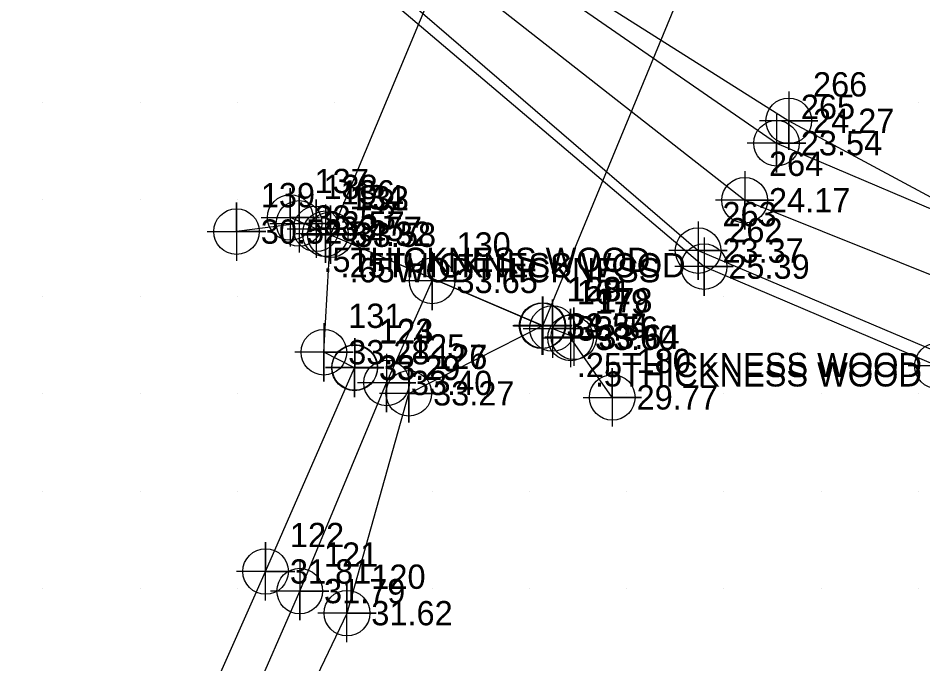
# Model space of a CAD drawing. Extents: x 2204340 to 2204783, y 268170 to 268760.
# Drawn here: x 2204477.4 to 2204570.5, y 268402.2 to 268468.7 of the extents above; entities that cross this region are included whole.
import ezdxf

# ---------------------------------------------------------------- set-up
doc = ezdxf.new("R2010")
doc.units = 0
for name, color, linetype in [('Exist DTM Breakline', 7, 'Continuous'), ('Exist DTM Breakline Cogo Elevation', 7, 'Continuous'), ('Exist DTM Breakline Cogo Number', 7, 'Continuous'), ('Exist DTM Breakline Cogo Point CELL', 7, 'Continuous'), ('Exist DTM Breakline Underwater', 7, 'Continuous'), ('Exist DTM Breakline Underwater Cogo Elevation', 7, 'Continuous'), ('Exist DTM Breakline Underwater Cogo Number', 7, 'Continuous'), ('Exist DTM Breakline Underwater Cogo Point CELL', 7, 'Continuous'), ('Exist DTM Crownline', 7, 'Continuous'), ('Exist DTM Crownline Cogo Elevation', 7, 'Continuous'), ('Exist DTM Crownline Cogo Number', 7, 'Continuous'), ('Exist DTM Crownline Cogo Point CELL', 7, 'Continuous'), ('Exist DTM QL2 LIDAR Elevation Point', 7, 'Continuous'), ('Exist Hydro Jurisdictional Stream or Body of Water', 7, 'Continuous'), ('Exist Roads Change in Surface', 7, 'Continuous'), ('Exist Roads Change in Surface Cogo Comment', 7, 'Continuous'), ('Exist Roads Change in Surface Cogo Elevation', 7, 'Continuous'), ('Exist Roads Change in Surface Cogo Number', 7, 'Continuous'), ('Exist Roads Change in Surface Cogo Point CELL', 7, 'Continuous'), ('Exist Roads EOP', 7, 'Continuous'), ('Exist Roads EOP Cogo Elevation', 7, 'Continuous'), ('Exist Roads EOP Cogo Number', 7, 'Continuous'), ('Exist Roads EOP Cogo Point CELL', 7, 'Continuous'), ('Exist Roads Soil', 7, 'Continuous'), ('Exist Roads Soil Cogo Elevation', 7, 'Continuous'), ('Exist Roads Soil Cogo Number', 7, 'Continuous'), ('Exist Roads Soil Cogo Point CELL', 7, 'Continuous'), ('Exist Structure Major Bridge WW', 7, 'Continuous'), ('Exist Structure Major Bridge WW Cogo Comment', 7, 'Continuous'), ('Exist Structure Major Bridge WW Cogo Elevation', 7, 'Continuous'), ('Exist Structure Major Bridge WW Cogo Number', 7, 'Continuous'), ('Exist Structure Major Bridge WW Cogo Point CELL', 7, 'Continuous'), ('Exist Structure Major Deck Tunnel Box Culvert', 7, 'Continuous'), ('Exist Structure Major Deck Tunnel Box Culvert Cogo Elevation', 7, 'Continuous'), ('Exist Structure Major Deck Tunnel Box Culvert Cogo Number', 7, 'Continuous'), ('Exist Structure Major Deck Tunnel Box Culvert Cogo Point CELL', 7, 'Continuous')]:
    doc.layers.add(name, color=color, linetype=linetype)

msp = doc.modelspace()

# ---------------------------------------------------------------- linework, layer by layer
at = {"layer": 'Exist DTM Breakline'}
for points in [[(2204442.107, 268518.107), (2204480.821, 268501.799), (2204502.532, 268495.779), (2204515.271, 268483.58), (2204555.414, 268455.782), (2204577.652, 268446.314), (2204630.936, 268427.717)], [(2204435.36, 268505.622), (2204480.446, 268489.144), (2204494.514, 268488.53), (2204511.374, 268475.793), (2204547.352, 268444.739), (2204573.727, 268433.567), (2204620.125, 268409.581)]]:
    msp.add_lwpolyline(points, dxfattribs=at)
at = {"layer": 'Exist DTM Breakline Cogo Point CELL'}
for points in [[(2204556.668, 268461.091), (2204556.668, 268455.091), (2204556.668, 268458.091), (2204559.668, 268458.091), (2204553.668, 268458.091)], [(2204555.413, 268458.782), (2204555.413, 268452.782), (2204555.413, 268455.782), (2204558.413, 268455.782), (2204552.413, 268455.782)], [(2204547.351, 268447.739), (2204547.351, 268441.739), (2204547.351, 268444.739), (2204550.351, 268444.739), (2204544.351, 268444.739)], [(2204547.96, 268446.09), (2204547.96, 268440.09), (2204547.96, 268443.09), (2204550.96, 268443.09), (2204544.96, 268443.09)], [(2204571.955, 268435.882), (2204571.955, 268429.882), (2204571.955, 268432.882), (2204574.955, 268432.882), (2204568.955, 268432.882)]]:
    msp.add_lwpolyline(points, dxfattribs=at)
for centre in [(2204556.668, 268458.091), (2204555.413, 268455.782), (2204547.351, 268444.739), (2204547.96, 268443.09), (2204571.955, 268432.882)]:
    msp.add_circle(centre, 2.344, dxfattribs=at)
at = {"layer": 'Exist DTM Breakline Underwater'}
msp.add_lwpolyline([(2204438.584, 268512.919), (2204481.572, 268495.841), (2204497.204, 268490.895), (2204514.255, 268479.669), (2204552.142, 268449.916), (2204575.996, 268440.349), (2204624.811, 268416.779)], dxfattribs=at)
at = {"layer": 'Exist DTM Breakline Underwater Cogo Point CELL'}
msp.add_lwpolyline([(2204552.141, 268452.916), (2204552.141, 268446.916), (2204552.141, 268449.916), (2204555.141, 268449.916), (2204549.141, 268449.916)], dxfattribs=at)
msp.add_circle((2204552.141, 268449.916), 2.344, dxfattribs=at)
at = {"layer": 'Exist DTM Crownline'}
msp.add_lwpolyline([(2204485.434, 268361.69), (2204506.392, 268409.717), (2204515.328, 268431.127), (2204520.013, 268441.62)], dxfattribs=at)
at = {"layer": 'Exist DTM Crownline Cogo Point CELL'}
for points in [[(2204520.012, 268444.62), (2204520.012, 268438.62), (2204520.012, 268441.62), (2204523.012, 268441.62), (2204517.012, 268441.62)], [(2204515.327, 268434.128), (2204515.327, 268428.128), (2204515.327, 268431.128), (2204518.327, 268431.128), (2204512.327, 268431.128)], [(2204506.391, 268412.716), (2204506.391, 268406.716), (2204506.391, 268409.716), (2204509.391, 268409.716), (2204503.391, 268409.716)]]:
    msp.add_lwpolyline(points, dxfattribs=at)
for centre in [(2204520.012, 268441.62), (2204515.327, 268431.128), (2204506.391, 268409.716)]:
    msp.add_circle(centre, 2.344, dxfattribs=at)
at = {"layer": 'Exist DTM QL2 LIDAR Elevation Point'}
for p, q in [((2204480, 268460), (2204480, 268460)), ((2204490, 268460), (2204490, 268460)), ((2204500, 268460), (2204500, 268460)), ((2204510, 268460), (2204510, 268460)), ((2204560, 268460), (2204560, 268460)), ((2204570, 268460), (2204570, 268460)), ((2204480, 268450), (2204480, 268450)), ((2204490, 268450), (2204490, 268450)), ((2204500, 268450), (2204500, 268450)), ((2204510, 268450), (2204510, 268450)), ((2204480, 268440), (2204480, 268440)), ((2204490, 268440), (2204490, 268440)), ((2204500, 268440), (2204500, 268440)), ((2204540, 268440), (2204540, 268440)), ((2204550, 268440), (2204550, 268440)), ((2204480, 268430), (2204480, 268430)), ((2204490, 268430), (2204490, 268430)), ((2204500, 268430), (2204500, 268430)), ((2204530, 268430), (2204530, 268430)), ((2204540, 268430), (2204540, 268430)), ((2204550, 268430), (2204550, 268430)), ((2204560, 268430), (2204560, 268430)), ((2204570, 268430), (2204570, 268430)), ((2204480, 268420), (2204480, 268420)), ((2204490, 268420), (2204490, 268420)), ((2204500, 268420), (2204500, 268420)), ((2204520, 268420), (2204520, 268420)), ((2204530, 268420), (2204530, 268420)), ((2204540, 268420), (2204540, 268420)), ((2204550, 268420), (2204550, 268420)), ((2204560, 268420), (2204560, 268420)), ((2204570, 268420), (2204570, 268420)), ((2204480, 268410), (2204480, 268410)), ((2204490, 268410), (2204490, 268410)), ((2204500, 268410), (2204500, 268410)), ((2204520, 268410), (2204520, 268410)), ((2204530, 268410), (2204530, 268410)), ((2204540, 268410), (2204540, 268410)), ((2204550, 268410), (2204550, 268410)), ((2204560, 268410), (2204560, 268410)), ((2204570, 268410), (2204570, 268410))]:
    msp.add_line(p, q, dxfattribs=at)
at = {"layer": 'Exist Hydro Jurisdictional Stream or Body of Water'}
for points in [[(2204442.883, 268520.114), (2204480.525, 268503.556), (2204503.227, 268495.899), (2204516.012, 268483.845), (2204556.669, 268458.091), (2204576.766, 268447.287), (2204631.194, 268429.043)], [(2204434.671, 268504.229), (2204475.094, 268482.789), (2204492.089, 268478.069), (2204511.02, 268474.48), (2204547.961, 268443.09), (2204571.955, 268432.882), (2204619.17, 268408.087)]]:
    msp.add_lwpolyline(points, dxfattribs=at)
at = {"layer": 'Exist Roads Change in Surface'}
msp.add_line((2204509.544, 268446.37), (2204531.394, 268437.027), dxfattribs=at)
at = {"layer": 'Exist Roads Change in Surface Cogo Point CELL'}
for points in [[(2204509.029, 268449.474), (2204509.029, 268443.474), (2204509.029, 268446.474), (2204512.029, 268446.474), (2204506.029, 268446.474)], [(2204531.311, 268440.011), (2204531.311, 268434.011), (2204531.311, 268437.011), (2204534.311, 268437.011), (2204528.311, 268437.011)]]:
    msp.add_lwpolyline(points, dxfattribs=at)
for centre in [(2204509.029, 268446.474), (2204531.311, 268437.011)]:
    msp.add_circle(centre, 2.344, dxfattribs=at)
at = {"layer": 'Exist Roads EOP'}
for points in [[(2204512.037, 268432.663), (2204508.88, 268434.285), (2204509.544, 268446.37)], [(2204517.609, 268430.056), (2204531.394, 268437.027)]]:
    msp.add_lwpolyline(points, dxfattribs=at)
at = {"layer": 'Exist Roads EOP Cogo Point CELL'}
for points in [[(2204509.543, 268449.369), (2204509.543, 268443.369), (2204509.543, 268446.369), (2204512.543, 268446.369), (2204506.543, 268446.369)], [(2204531.393, 268440.026), (2204531.393, 268434.026), (2204531.393, 268437.026), (2204534.393, 268437.026), (2204528.393, 268437.026)], [(2204508.88, 268437.285), (2204508.88, 268431.285), (2204508.88, 268434.285), (2204511.88, 268434.285), (2204505.88, 268434.285)], [(2204512.037, 268435.664), (2204512.037, 268429.664), (2204512.037, 268432.664), (2204515.037, 268432.664), (2204509.037, 268432.664)], [(2204517.608, 268433.056), (2204517.608, 268427.056), (2204517.608, 268430.056), (2204520.608, 268430.056), (2204514.608, 268430.056)]]:
    msp.add_lwpolyline(points, dxfattribs=at)
for centre in [(2204509.543, 268446.369), (2204531.393, 268437.026), (2204508.88, 268434.285), (2204512.037, 268432.664), (2204517.608, 268430.056)]:
    msp.add_circle(centre, 2.344, dxfattribs=at)
at = {"layer": 'Exist Roads Soil'}
for points in [[(2204481.307, 268363.121), (2204502.888, 268411.733), (2204512.03, 268432.667)], [(2204488.581, 268360.035), (2204511.257, 268407.444), (2204517.609, 268430.056)]]:
    msp.add_lwpolyline(points, dxfattribs=at)
at = {"layer": 'Exist Roads Soil Cogo Point CELL'}
for points in [[(2204512.055, 268429.724), (2204512.055, 268435.724), (2204512.055, 268432.724), (2204515.055, 268432.724), (2204509.055, 268432.724)], [(2204517.608, 268427.056), (2204517.608, 268433.056), (2204517.608, 268430.056), (2204520.608, 268430.056), (2204514.608, 268430.056)], [(2204502.888, 268408.733), (2204502.888, 268414.733), (2204502.888, 268411.733), (2204505.888, 268411.733), (2204499.888, 268411.733)], [(2204511.256, 268404.443), (2204511.256, 268410.443), (2204511.256, 268407.443), (2204514.256, 268407.443), (2204508.256, 268407.443)]]:
    msp.add_lwpolyline(points, dxfattribs=at)
for centre in [(2204512.055, 268432.724), (2204517.608, 268430.056), (2204502.888, 268411.733), (2204511.256, 268407.443)]:
    msp.add_circle(centre, 2.344, dxfattribs=at)
at = {"layer": 'Exist Structure Major Bridge WW'}
for points in [[(2204508.089, 268446.982), (2204505.422, 268448.148)], [(2204506.329, 268447.54), (2204499.897, 268446.696)], [(2204532.386, 268436.722), (2204534.586, 268435.88)], [(2204538.529, 268429.64), (2204534.242, 268435.758)]]:
    msp.add_lwpolyline(points, dxfattribs=at)
at = {"layer": 'Exist Structure Major Bridge WW Cogo Point CELL'}
for points in [[(2204502.422, 268448.148), (2204508.422, 268448.148), (2204505.422, 268448.148), (2204505.422, 268451.148), (2204505.422, 268445.148)], [(2204503.329, 268447.54), (2204509.329, 268447.54), (2204506.329, 268447.54), (2204506.329, 268450.54), (2204506.329, 268444.54)], [(2204496.896, 268446.696), (2204502.896, 268446.696), (2204499.896, 268446.696), (2204499.896, 268449.696), (2204499.896, 268443.696)], [(2204505.089, 268446.982), (2204511.089, 268446.982), (2204508.089, 268446.982), (2204508.089, 268449.982), (2204508.089, 268443.982)], [(2204529.385, 268436.722), (2204535.385, 268436.722), (2204532.385, 268436.722), (2204532.385, 268439.722), (2204532.385, 268433.722)], [(2204531.241, 268435.758), (2204537.241, 268435.758), (2204534.241, 268435.758), (2204534.241, 268438.758), (2204534.241, 268432.758)], [(2204531.586, 268435.88), (2204537.586, 268435.88), (2204534.586, 268435.88), (2204534.586, 268438.88), (2204534.586, 268432.88)], [(2204535.529, 268429.64), (2204541.529, 268429.64), (2204538.529, 268429.64), (2204538.529, 268432.64), (2204538.529, 268426.64)]]:
    msp.add_lwpolyline(points, dxfattribs=at)
for centre in [(2204505.422, 268448.148), (2204506.329, 268447.54), (2204499.896, 268446.696), (2204508.089, 268446.982), (2204532.385, 268436.722), (2204534.241, 268435.758), (2204534.586, 268435.88), (2204538.529, 268429.64)]:
    msp.add_circle(centre, 2.344, dxfattribs=at)
at = {"layer": 'Exist Structure Major Deck Tunnel Box Culvert'}
msp.add_lwpolyline([(2204531.382, 268437.017), (2204551.027, 268484.531), (2204529.29, 268493.682), (2204509.543, 268446.369)], close=True, dxfattribs=at)
at = {"layer": 'Exist Structure Major Deck Tunnel Box Culvert Cogo Point CELL'}
for points in [[(2204506.543, 268446.369), (2204512.543, 268446.369), (2204509.543, 268446.369), (2204509.543, 268449.369), (2204509.543, 268443.369)], [(2204528.382, 268437.017), (2204534.382, 268437.017), (2204531.382, 268437.017), (2204531.382, 268440.017), (2204531.382, 268434.017)]]:
    msp.add_lwpolyline(points, dxfattribs=at)
for centre in [(2204509.543, 268446.369), (2204531.382, 268437.017)]:
    msp.add_circle(centre, 2.344, dxfattribs=at)

# ---------------------------------------------------------------- texts
at = {"layer": 'Exist DTM Breakline Cogo Elevation'}
for s, p in [('24.27', (2204559.168, 268456.841)), ('23.54', (2204557.913, 268454.532)), ('23.37', (2204549.851, 268443.489)), ('25.39', (2204550.46, 268441.84))]:
    msp.add_text(s, height=2.5, dxfattribs=at).set_placement(p)
at = {"layer": 'Exist DTM Breakline Cogo Number'}
for s, p in [('266', (2204559.168, 268460.591)), ('265', (2204557.913, 268458.282)), ('263', (2204549.851, 268447.239)), ('262', (2204550.46, 268445.59))]:
    msp.add_text(s, height=2.5, dxfattribs=at).set_placement(p)
at = {"layer": 'Exist DTM Breakline Underwater Cogo Elevation'}
msp.add_text('24.17', height=2.5, dxfattribs=at).set_placement((2204554.641, 268448.666))
at = {"layer": 'Exist DTM Breakline Underwater Cogo Number'}
msp.add_text('264', height=2.5, dxfattribs=at).set_placement((2204554.641, 268452.416))
at = {"layer": 'Exist DTM Crownline Cogo Elevation'}
for s, p in [('33.65', (2204522.512, 268440.37)), ('33.40', (2204517.827, 268429.878)), ('31.79', (2204508.891, 268408.466))]:
    msp.add_text(s, height=2.5, dxfattribs=at).set_placement(p)
at = {"layer": 'Exist DTM Crownline Cogo Number'}
for s, p in [('130', (2204522.512, 268444.12)), ('125', (2204517.827, 268433.628)), ('121', (2204508.891, 268412.216))]:
    msp.add_text(s, height=2.5, dxfattribs=at).set_placement(p)
at = {"layer": 'Exist Roads Change in Surface Cogo Comment'}
msp.add_text('.65WODTHICKNESS', height=2.5, dxfattribs=at).set_placement((2204511.529, 268441.474))
at = {"layer": 'Exist Roads Change in Surface Cogo Elevation'}
for s, p in [('34.32', (2204511.529, 268445.224)), ('34.35', (2204533.811, 268435.761))]:
    msp.add_text(s, height=2.5, dxfattribs=at).set_placement(p)
at = {"layer": 'Exist Roads Change in Surface Cogo Number'}
for s, p in [('134', (2204511.529, 268448.974)), ('158', (2204533.811, 268439.511))]:
    msp.add_text(s, height=2.5, dxfattribs=at).set_placement(p)
at = {"layer": 'Exist Roads EOP Cogo Elevation'}
for s, p in [('33.58', (2204512.043, 268445.119)), ('33.54', (2204533.893, 268435.776)), ('33.28', (2204511.38, 268433.035)), ('33.29', (2204514.537, 268431.414)), ('33.27', (2204520.108, 268428.806))]:
    msp.add_text(s, height=2.5, dxfattribs=at).set_placement(p)
at = {"layer": 'Exist Roads EOP Cogo Number'}
for s, p in [('132', (2204512.043, 268448.869)), ('128', (2204533.893, 268439.526)), ('131', (2204511.38, 268436.785)), ('124', (2204514.537, 268435.164)), ('127', (2204520.108, 268432.556))]:
    msp.add_text(s, height=2.5, dxfattribs=at).set_placement(p)
at = {"layer": 'Exist Roads Soil Cogo Elevation'}
for s, p in [('33.29', (2204514.555, 268431.474)), ('33.27', (2204520.108, 268428.806)), ('31.81', (2204505.388, 268410.483)), ('31.62', (2204513.756, 268406.193))]:
    msp.add_text(s, height=2.5, dxfattribs=at).set_placement(p)
at = {"layer": 'Exist Roads Soil Cogo Number'}
for s, p in [('123', (2204514.555, 268435.224)), ('126', (2204520.108, 268432.556)), ('122', (2204505.388, 268414.233)), ('120', (2204513.756, 268409.943))]:
    msp.add_text(s, height=2.5, dxfattribs=at).set_placement(p)
at = {"layer": 'Exist Structure Major Bridge WW Cogo Comment'}
for s, p in [('.5THICKNESS WOOD', (2204508.829, 268442.54)), ('.25THICKNESS WOOD', (2204510.589, 268441.982)), ('.25THICKNESS WOOD', (2204534.885, 268431.722)), ('.5THICKNESS WOOD', (2204536.741, 268430.758))]:
    msp.add_text(s, height=2.5, dxfattribs=at).set_placement(p)
at = {"layer": 'Exist Structure Major Bridge WW Cogo Elevation'}
for s, p in [('33.53', (2204507.922, 268446.898)), ('33.57', (2204508.829, 268446.29)), ('30.52', (2204502.396, 268445.446)), ('33.57', (2204510.589, 268445.732)), ('33.56', (2204534.885, 268435.472)), ('33.60', (2204536.741, 268434.508)), ('33.64', (2204537.086, 268434.63)), ('29.77', (2204541.029, 268428.39))]:
    msp.add_text(s, height=2.5, dxfattribs=at).set_placement(p)
at = {"layer": 'Exist Structure Major Bridge WW Cogo Number'}
for s, p in [('137', (2204507.922, 268450.648)), ('138', (2204508.829, 268450.04)), ('139', (2204502.396, 268449.196)), ('136', (2204510.589, 268449.482)), ('161', (2204534.885, 268439.222)), ('179', (2204536.741, 268438.258)), ('178', (2204537.086, 268438.38)), ('180', (2204541.029, 268432.14))]:
    msp.add_text(s, height=2.5, dxfattribs=at).set_placement(p)
at = {"layer": 'Exist Structure Major Deck Tunnel Box Culvert Cogo Elevation'}
for s, p in [('33.58', (2204512.043, 268445.119)), ('33.54', (2204533.882, 268435.767))]:
    msp.add_text(s, height=2.5, dxfattribs=at).set_placement(p)
at = {"layer": 'Exist Structure Major Deck Tunnel Box Culvert Cogo Number'}
for s, p in [('133', (2204512.043, 268448.869)), ('129', (2204533.882, 268439.517))]:
    msp.add_text(s, height=2.5, dxfattribs=at).set_placement(p)

doc.saveas('drawing.dxf')
